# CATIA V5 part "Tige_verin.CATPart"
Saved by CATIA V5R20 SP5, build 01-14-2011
Part number: Tige_verin
Publications: "Droite.1", "Droite.2"
Bounding box of the stored display mesh (mm): x -200 to 0, y 233.933 to 618.933, z 128.204 to 128.204
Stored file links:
  J:\Thinkmotion\Projet IAO\A envoyer\Tige_verin.CATPart
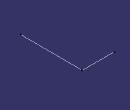
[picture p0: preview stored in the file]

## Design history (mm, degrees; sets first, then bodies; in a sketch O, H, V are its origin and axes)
Set1
  Line1: type PtPt, FirstPoint Point1, SecondPoint Point2
  Point1 "V": stored without definition
  Point2 "E": stored without definition
  Line2: type Normal, RefPoint Point3, RefSkin yz-plane, Start 0, End -200
  Point3 "E": stored without definition
Body1 (main body)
